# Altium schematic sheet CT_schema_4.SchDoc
size 298 x 247 mm
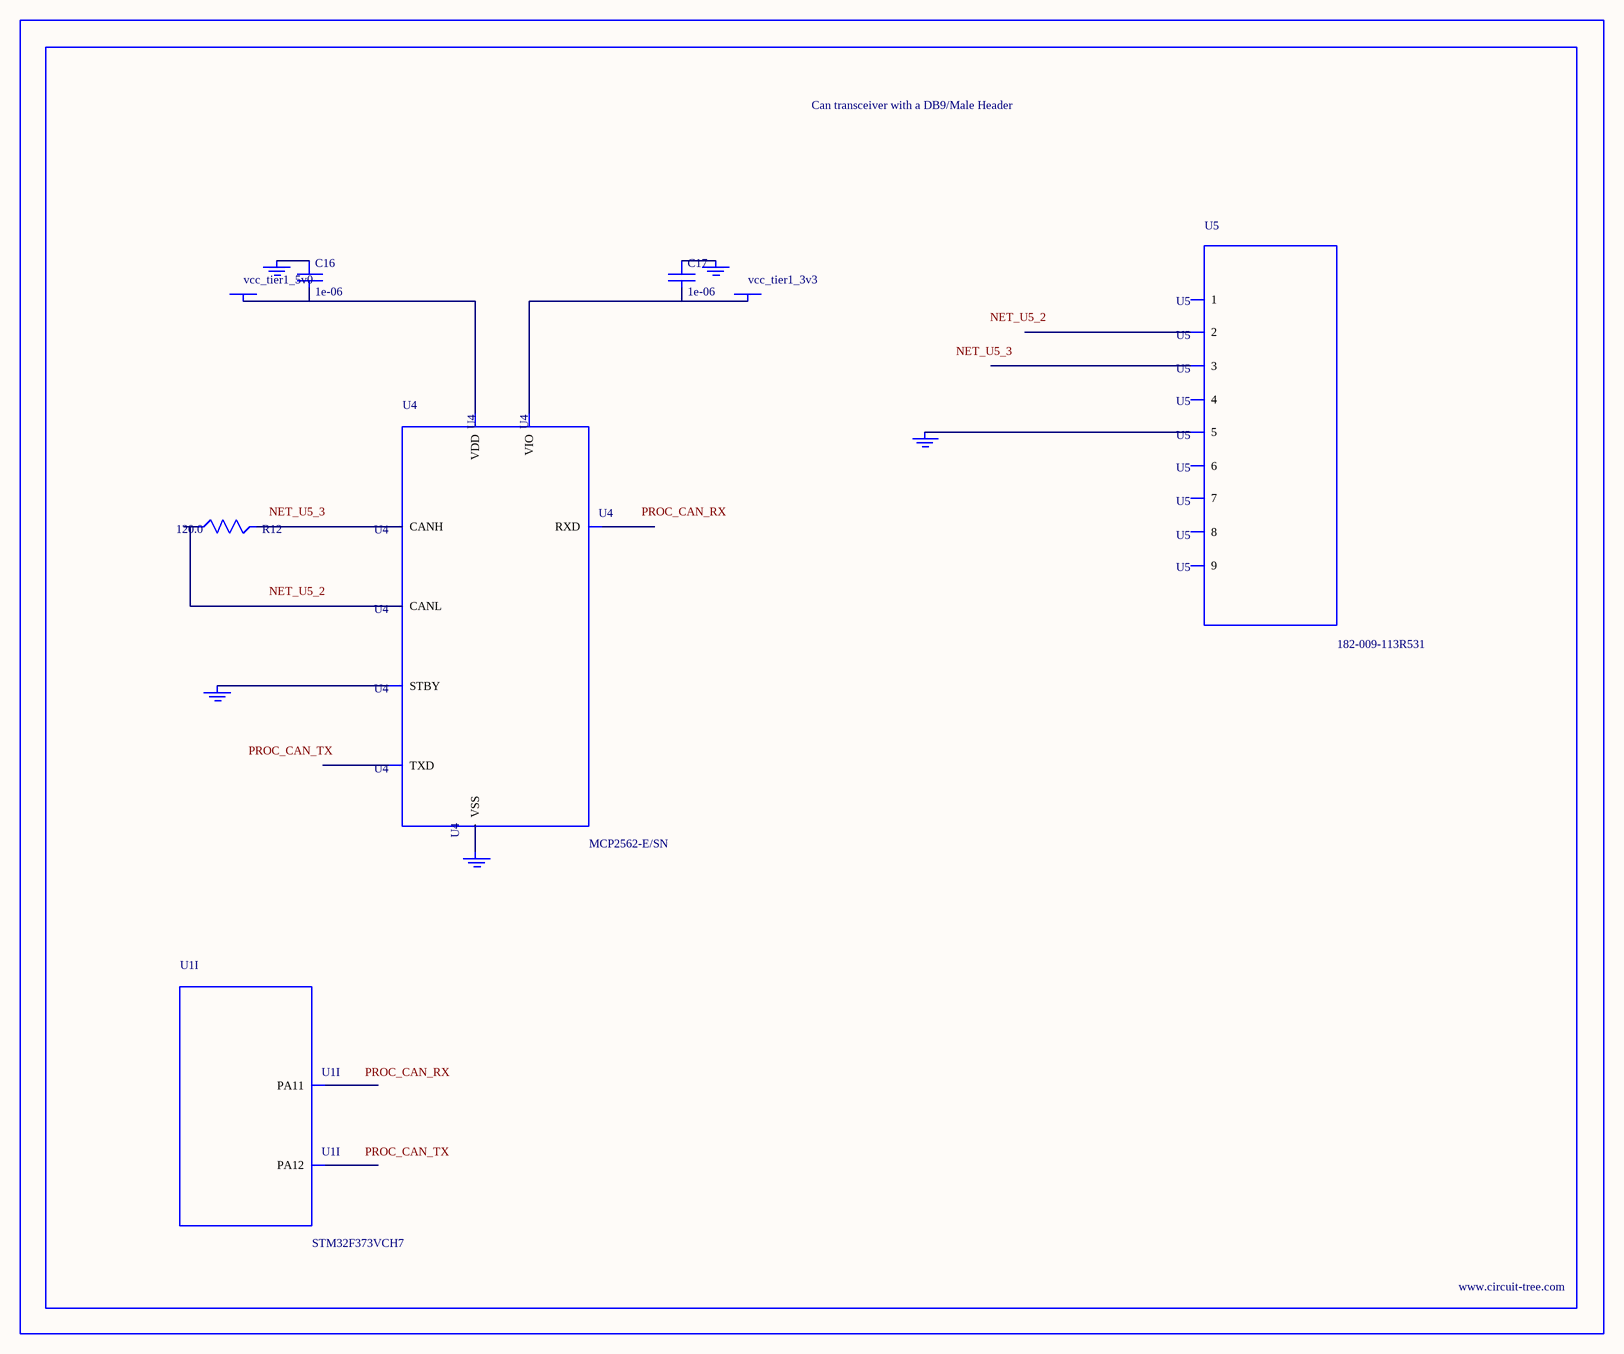
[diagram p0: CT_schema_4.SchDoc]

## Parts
BORDER3  (no value)
C16  1e-06  [C0603]
C17  1e-06  [C0603]
GND_INSTANCE_3_0  (no value)
GND_INSTANCE_3_1  (no value)
GND_INSTANCE_3_2  (no value)
GND_INSTANCE_3_3  (no value)
GND_INSTANCE_3_4  (no value)
POWER_INSTANCE_3_0  vcc_tier1_5v0
POWER_INSTANCE_3_1  vcc_tier1_3v3
R12  120.0  [R0603]
U1  STM32F373VCH7  [UFBGA100]  (part I of 10)
U4  MCP2562-E/SN  [SOIC-8]
U5  182-009-113R531  [182-009-MALE]

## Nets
NetC16_1: C16.1 GND_INSTANCE_3_0.0(GND)
NetC16_2: C16.2 POWER_INSTANCE_3_0.0(PWR) U4.3(VDD)
NetC17_1: C17.1 GND_INSTANCE_3_1.0(GND)
NetC17_2: C17.2 POWER_INSTANCE_3_1.0(PWR) U4.5(VIO)
NetGND_INSTANCE_3_2_0: GND_INSTANCE_3_2.0(GND) U4.8(STBY)
NetGND_INSTANCE_3_3_0: GND_INSTANCE_3_3.0(GND) U4.2(VSS)
NetGND_INSTANCE_3_4_0: GND_INSTANCE_3_4.0(GND) U5.5
NetR12_1: R12.1 U4.6(CANL)
NetR12_2: R12.2 U4.7(CANH)

Not connected (* = marked no-connect by the designer): U1 A12(PA12) B12(PA11); U4 1(TXD) 4(RXD); U5 1 2 3 4 6 7 8 9

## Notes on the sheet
- Labels drawn without touching a wire or pin: NET_U5_2, NET_U5_3, PROC_CAN_RX, PROC_CAN_TX

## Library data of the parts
BORDER3 = BORDER_PAGE3
C16 C17 = C0603C105K3RACTU
GND_INSTANCE_3_0-GND_INSTANCE_3_4 = GND
POWER_INSTANCE_3_0 POWER_INSTANCE_3_1 = PWR
R12 = RC0603JR-07120RL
